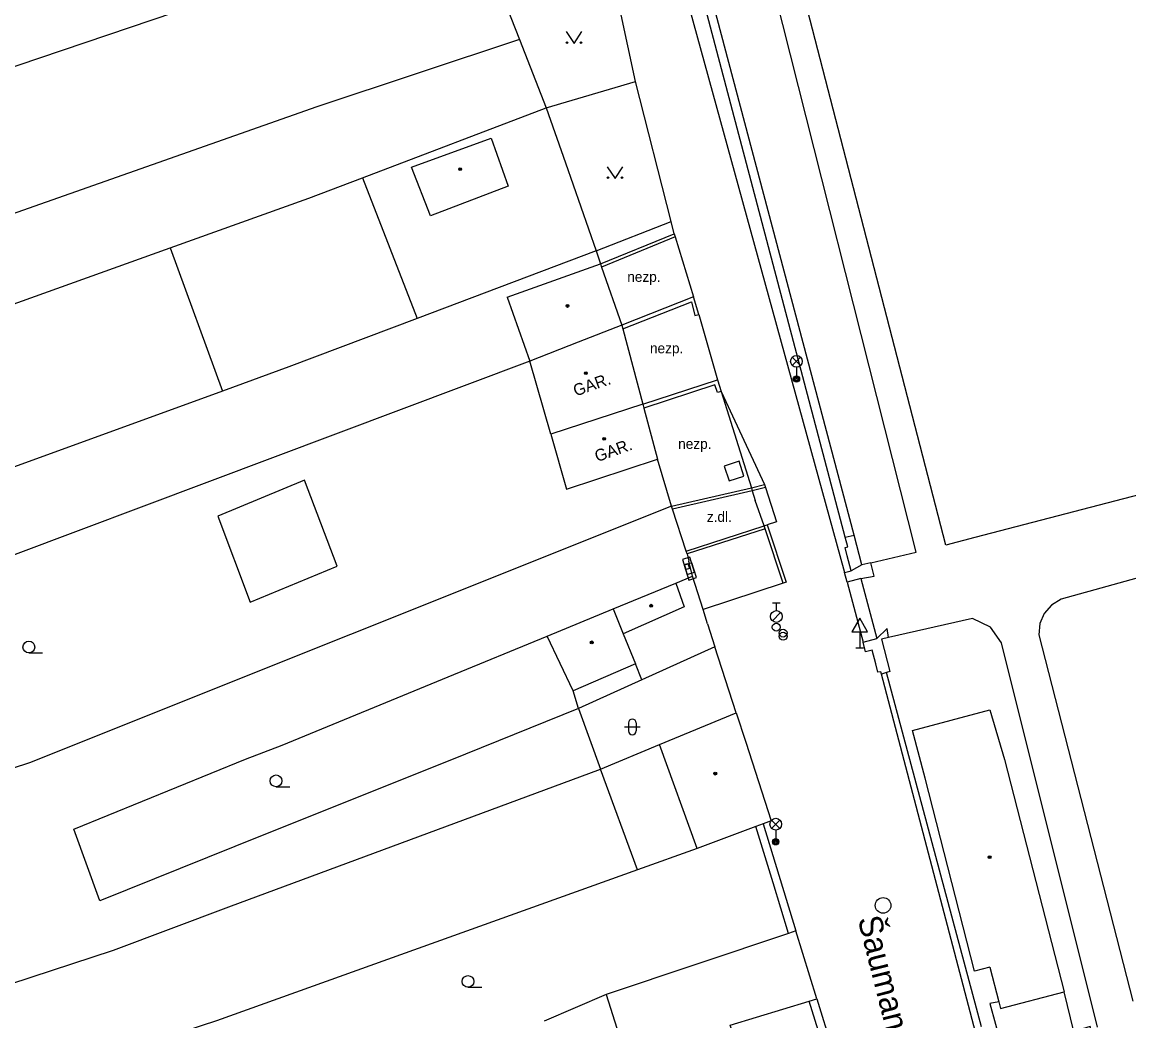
# Model space of a CAD drawing. Extents: x -595546 to -593986, y -1160845 to -1159202.
# Drawn here: x -595377.5 to -595306.9, y -1160103.9 to -1160040.2 of the extents above; entities that cross this region are included whole.
import ezdxf

# ---------------------------------------------------------------- set-up
doc = ezdxf.new("R2010")
doc.units = 0
for name, color, linetype in [('DOP - budovy nerozlisene - VP', 7, 'Continuous'), ('DOP - kresba z DSPS bez souradnic', 7, 'Continuous'), ('DOP - rozhrani ploch obecne', 7, 'Continuous'), ('Level 24', 7, 'Continuous'), ('Level 26', 7, 'Continuous'), ('Level 27', 7, 'Continuous'), ('Level 28', 7, 'Continuous'), ('Level 33', 7, 'Continuous'), ('Level 34', 7, 'Continuous'), ('Level 36', 7, 'Continuous'), ('Level 39', 7, 'Continuous'), ('Nazvy ulic', 7, 'Continuous'), ('silnoproud - povrch.  znaky a  RIS  skut. velikost', 7, 'Continuous'), ('Specificka linie pasportu komunikaci', 7, 'Continuous'), ('TM - budovy zdene_ betonove - VP', 7, 'Continuous'), ('TM - chodniky - VP', 7, 'Continuous'), ('TM - komunikace - VP', 7, 'Continuous'), ('TM - letecke snimky - pomocna linie', 7, 'Continuous'), ('TM - plot drateny_ kovovy - VP', 7, 'Continuous'), ('TM - podezdivka plotu - VP', 7, 'Continuous'), ('TM - popis objektu', 7, 'Continuous'), ('TM - popis povrchu', 7, 'Continuous'), ('TM - rozhrani ploch obecne - VP', 7, 'Continuous'), ('TM - vjezd na pozemek', 7, 'Continuous')]:
    doc.layers.add(name, color=color, linetype=linetype)

msp = doc.modelspace()

# ---------------------------------------------------------------- linework, layer by layer
at = {"layer": 'DOP - budovy nerozlisene - VP'}
for points in [[(-595352.7, -1160049.44), (-595347.6, -1160047.6)], [(-595347.6, -1160047.6), (-595346.52, -1160050.65)], [(-595351.49, -1160052.54), (-595352.7, -1160049.44)], [(-595346.52, -1160050.65), (-595351.49, -1160052.54)]]:
    msp.add_lwpolyline(points, dxfattribs=at)
at = {"layer": 'DOP - kresba z DSPS bez souradnic'}
for points in [[(-595320.47, -1160074.01), (-595330.51, -1160034.34), (-595292.71, -1160024.25)], [(-595318.59, -1160073.57), (-595327.9, -1160037.48), (-595292.42, -1160027.98)], [(-595283.02, -1160064.31), (-595316.73, -1160073.08), (-595318.59, -1160073.57)], [(-595276.28, -1160087.45), (-595280.92, -1160070.28), (-595281.28, -1160069.71), (-595281.79, -1160069.34), (-595282.39, -1160069.15), (-595283.06, -1160069.2), (-595311.22, -1160077.02)], [(-595311.22, -1160077.02), (-595311.84, -1160077.39), (-595312.31, -1160077.92), (-595312.58, -1160078.57), (-595312.64, -1160079.3), (-595306.64, -1160102.66)], [(-595315.73, -1160078.79), (-595316.88, -1160078.25)], [(-595315.02, -1160079.8), (-595315.73, -1160078.79)], [(-595308.9, -1160104.34), (-595315.02, -1160079.8)]]:
    msp.add_lwpolyline(points, dxfattribs=at)
at = {"layer": 'DOP - rozhrani ploch obecne'}
for points in [[(-595397.89, -1160049.71), (-595349.19, -1160033.22)], [(-595345.8, -1160041.3), (-595358.73, -1160045.59)], [(-595358.73, -1160045.59), (-595440.25, -1160074.28)], [(-595355.83, -1160050.13), (-595344.09, -1160045.65)], [(-595359.25, -1160051.43), (-595355.83, -1160050.13)], [(-595368.1, -1160054.6), (-595359.25, -1160051.43)], [(-595438.69, -1160079.91), (-595368.1, -1160054.6)], [(-595340.91, -1160054.79), (-595352.34, -1160059.1)], [(-595352.34, -1160059.1), (-595360.52, -1160062.19)], [(-595345.13, -1160061.83), (-595398.63, -1160081.9)], [(-595360.52, -1160062.19), (-595364.76, -1160063.73)], [(-595364.76, -1160063.73), (-595435.62, -1160089.5)], [(-595336.1, -1160071.08), (-595377.07, -1160087.46)], [(-595350.35, -1160081.96), (-595344.04, -1160079.37)], [(-595360.95, -1160086.34), (-595350.35, -1160081.96)], [(-595342.03, -1160084), (-595349.24, -1160086.91)], [(-595342.03, -1160084), (-595340.62, -1160087.86)], [(-595363.3, -1160087.23), (-595360.95, -1160086.34)], [(-595340.62, -1160087.86), (-595336.87, -1160086.29)], [(-595349.24, -1160086.91), (-595363.97, -1160092.79)], [(-595377.07, -1160087.46), (-595386.34, -1160090.48)], [(-595374.26, -1160091.7), (-595363.3, -1160087.23)], [(-595364.35, -1160096.65), (-595340.62, -1160087.86)], [(-595338.27, -1160094.29), (-595340.62, -1160087.86)], [(-595372.59, -1160096.27), (-595374.26, -1160091.7)], [(-595363.97, -1160092.79), (-595372.59, -1160096.27)], [(-595334.45, -1160092.92), (-595338.27, -1160094.29)], [(-595338.27, -1160094.29), (-595365.15, -1160103.92)], [(-595371.72, -1160099.41), (-595364.35, -1160096.65)], [(-595423.07, -1160116.24), (-595371.72, -1160099.41)], [(-595340.26, -1160102.25), (-595344.23, -1160103.94)], [(-595365.15, -1160103.92), (-595372.18, -1160106.22)]]:
    msp.add_lwpolyline(points, dxfattribs=at)
at = {"layer": 'Level 24'}
for points in [[(-595334.618, -1160075.291), (-595334.916, -1160074.336), (-595335.393, -1160074.486), (-595335.095, -1160075.44)], [(-595334.507, -1160075.64), (-595334.807, -1160074.686), (-595335.284, -1160074.836), (-595334.984, -1160075.79)]]:
    msp.add_lwpolyline(points, close=True, dxfattribs=at)
at = {"layer": 'Level 26'}
msp.add_lwpolyline([(-595332.423, -1160069.469), (-595331.471, -1160069.163), (-595331.777, -1160068.211), (-595332.729, -1160068.517)], close=True, dxfattribs=at)
at = {"layer": 'Level 27'}
msp.add_circle((-595322.59, -1160096.56), 0.5, dxfattribs=at)
at = {"layer": 'Level 28'}
for p, q in [((-595329.658, -1160078.392), (-595329.128, -1160077.862)), ((-595329.65, -1160077.245), (-595329.15, -1160077.245)), ((-595329.4, -1160077.745), (-595329.4, -1160077.245))]:
    msp.add_line(p, q, dxfattribs=at)
for centre, radius in [((-595329.4, -1160078.12), 0.375), ((-595329.41, -1160078.8), 0.25), ((-595328.97, -1160079.18), 0.25), ((-595328.97, -1160079.38), 0.25)]:
    msp.add_circle(centre, radius, dxfattribs=at)
at = {"layer": 'Level 33'}
for p, q in [((-595328.385, -1160062.1), (-595327.855, -1160061.57)), ((-595328.385, -1160061.57), (-595327.855, -1160062.1)), ((-595328.12, -1160062.21), (-595328.12, -1160062.96)), ((-595329.705, -1160091.64), (-595329.175, -1160091.11)), ((-595329.705, -1160091.11), (-595329.175, -1160091.64)), ((-595329.44, -1160091.75), (-595329.44, -1160092.5))]:
    msp.add_line(p, q, dxfattribs=at)
for centre, radius in [((-595328.12, -1160061.835), 0.375), ((-595328.12, -1160062.96), 0.2), ((-595328.12, -1160062.96), 0.145), ((-595328.12, -1160062.96), 0.0876), ((-595329.44, -1160091.375), 0.375), ((-595329.44, -1160092.5), 0.2), ((-595329.44, -1160092.5), 0.145), ((-595329.44, -1160092.5), 0.0876)]:
    msp.add_circle(centre, radius, dxfattribs=at)
at = {"layer": 'Level 34'}
for p, q in [((-595324.08, -1160079.102), (-595324.08, -1160080.12)), ((-595324.33, -1160080.12), (-595323.83, -1160080.12))]:
    msp.add_line(p, q, dxfattribs=at)
msp.add_lwpolyline([(-595324.58, -1160079.102), (-595323.58, -1160079.102), (-595324.08, -1160078.236)], close=True, dxfattribs=at)
at = {"layer": 'Level 36'}
for p, q in [((-595377.12, -1160080.445), (-595376.245, -1160080.445)), ((-595338.846, -1160084.916), (-595338.846, -1160085.416)), ((-595338.346, -1160084.916), (-595338.346, -1160085.416)), ((-595339.096, -1160085.166), (-595338.096, -1160085.166)), ((-595361.34, -1160088.985), (-595360.465, -1160088.985)), ((-595349.09, -1160101.785), (-595348.215, -1160101.785))]:
    msp.add_line(p, q, dxfattribs=at)
for points in [[(-595342.82, -1160040.79), (-595342.32, -1160041.54), (-595341.82, -1160040.79)], [(-595340.2, -1160049.41), (-595339.7, -1160050.16), (-595339.2, -1160049.41)]]:
    msp.add_lwpolyline(points, dxfattribs=at)
for centre, radius in [((-595342.77, -1160041.49), 0.05), ((-595341.871, -1160041.49), 0.05), ((-595340.15, -1160050.11), 0.05), ((-595339.251, -1160050.11), 0.05), ((-595377.12, -1160080.07), 0.375), ((-595361.34, -1160088.61), 0.375), ((-595349.09, -1160101.41), 0.375)]:
    msp.add_circle(centre, radius, dxfattribs=at)
for centre, start, end in [((-595338.596, -1160084.916), 0, 180), ((-595338.596, -1160085.416), 180, 0)]:
    msp.add_arc(centre, 0.25, start, end, dxfattribs=at)
at = {"layer": 'Level 39'}
for centre, radius in [((-595349.59, -1160049.57), 0.09), ((-595349.59, -1160049.57), 0.0398), ((-595342.73, -1160058.3), 0.09), ((-595342.73, -1160058.3), 0.0398), ((-595341.57, -1160062.59), 0.09), ((-595341.57, -1160062.59), 0.0398), ((-595340.39, -1160066.78), 0.09), ((-595340.39, -1160066.78), 0.0398), ((-595337.39, -1160077.43), 0.09), ((-595337.39, -1160077.43), 0.0398), ((-595341.19, -1160079.77), 0.09), ((-595341.19, -1160079.77), 0.0398), ((-595333.3, -1160088.15), 0.09), ((-595333.3, -1160088.15), 0.0398), ((-595315.79, -1160093.48), 0.09), ((-595315.79, -1160093.48), 0.0398)]:
    msp.add_circle(centre, radius, dxfattribs=at)
at = {"layer": 'silnoproud - povrch.  znaky a  RIS  skut. velikost'}
msp.add_lwpolyline([(-595334.95, -1160075.06), (-595335.16, -1160075.13), (-595335.26, -1160074.81), (-595335.05, -1160074.74), (-595334.95, -1160075.06)], dxfattribs=at)
at = {"layer": 'Specificka linie pasportu komunikaci'}
for points in [[(-595340.91, -1160054.79), (-595336.12, -1160052.9)], [(-595332.92, -1160063.75), (-595331, -1160069.9)], [(-595331, -1160069.9), (-595330.94, -1160070.09)], [(-595330.94, -1160070.09), (-595330.75, -1160070.71)], [(-595330.18, -1160072.33), (-595330.75, -1160070.71)], [(-595330.12, -1160072.52), (-595330.18, -1160072.33)]]:
    msp.add_lwpolyline(points, dxfattribs=at)
at = {"layer": 'TM - budovy zdene_ betonove - VP'}
for points in [[(-595346.59, -1160057.73), (-595340.63, -1160055.61)], [(-595340.63, -1160055.61), (-595340.56, -1160055.82)], [(-595340.56, -1160055.82), (-595339.27, -1160059.52)], [(-595346.59, -1160057.73), (-595345.13, -1160061.83)], [(-595339.27, -1160059.52), (-595342.06, -1160060.62)], [(-595339.27, -1160059.52), (-595339.21, -1160059.76)], [(-595339.21, -1160059.76), (-595337.93, -1160064.57)], [(-595342.06, -1160060.62), (-595345.13, -1160061.83)], [(-595343.8, -1160066.48), (-595345.13, -1160061.83)], [(-595337.93, -1160064.57), (-595343.8, -1160066.48)], [(-595337.93, -1160064.57), (-595337.86, -1160064.82)], [(-595337.86, -1160064.82), (-595336.99, -1160068.08)], [(-595343.8, -1160066.48), (-595342.79, -1160069.99)], [(-595342.79, -1160069.99), (-595336.99, -1160068.08)], [(-595339.82, -1160077.63), (-595335.81, -1160075.99)], [(-595335.81, -1160075.99), (-595335.29, -1160077.51)], [(-595344.04, -1160079.37), (-595339.82, -1160077.63)], [(-595339.82, -1160077.63), (-595339.18, -1160079.23)], [(-595335.29, -1160077.51), (-595339.18, -1160079.23)], [(-595339.18, -1160079.23), (-595338.4, -1160081.14)], [(-595342.37, -1160082.86), (-595344.04, -1160079.37)], [(-595338.4, -1160081.14), (-595342.37, -1160082.86)], [(-595336.87, -1160086.29), (-595331.97, -1160084.26)], [(-595331.97, -1160084.26), (-595331.36, -1160086.15)], [(-595334.45, -1160092.92), (-595336.87, -1160086.29)], [(-595331.36, -1160086.15), (-595329.74, -1160091.17)], [(-595314.84, -1160087.25), (-595311.02, -1160102.08)], [(-595316.76, -1160100.75), (-595319.91, -1160088.43)], [(-595330.24, -1160091.35), (-595330.71, -1160091.53)], [(-595329.74, -1160091.17), (-595330.24, -1160091.35)], [(-595330.71, -1160091.53), (-595334.45, -1160092.92)], [(-595315.78, -1160100.49), (-595316.76, -1160100.75)], [(-595315.78, -1160100.49), (-595315.21, -1160102.71)], [(-595315.1, -1160103.13), (-595311.02, -1160102.08)], [(-595315.21, -1160102.71), (-595315.1, -1160103.13)]]:
    msp.add_lwpolyline(points, dxfattribs=at)
at = {"layer": 'TM - chodniky - VP'}
for points in [[(-595323.38, -1160074.7), (-595320.47, -1160074.01)], [(-595316.88, -1160078.25), (-595322.25, -1160079.45)]]:
    msp.add_lwpolyline(points, dxfattribs=at)
at = {"layer": 'TM - komunikace - VP'}
for points in [[(-595338.4, -1160043.97), (-595340.78, -1160032.87)], [(-595335.91, -1160035.83), (-595325.05, -1160075.31)], [(-595336.12, -1160052.9), (-595338.4, -1160043.97)], [(-595335.92, -1160053.7), (-595336.12, -1160052.9)], [(-595335.86, -1160053.89), (-595334.69, -1160057.71)], [(-595334.36, -1160058.84), (-595333.16, -1160063.02)], [(-595332.92, -1160063.75), (-595330.15, -1160069.7)], [(-595330.09, -1160069.89), (-595329.4, -1160072.07), (-595329.99, -1160072.27)]]:
    msp.add_lwpolyline(points, dxfattribs=at)
at = {"layer": 'TM - letecke snimky - pomocna linie'}
for points in [[(-595355.83, -1160050.13), (-595352.34, -1160059.1)], [(-595368.1, -1160054.6), (-595364.76, -1160063.73)], [(-595359.52, -1160069.41), (-595365.05, -1160071.71), (-595362.99, -1160077.21)], [(-595362.99, -1160077.21), (-595357.45, -1160074.91), (-595359.52, -1160069.41)], [(-595328.97, -1160075.99), (-595334.08, -1160077.68)], [(-595319.91, -1160088.43), (-595320.71, -1160085.39), (-595315.77, -1160084.07), (-595314.84, -1160087.25)], [(-595328.62, -1160098.35), (-595340.26, -1160102.25)], [(-595328.15, -1160098.18), (-595328.62, -1160098.35)], [(-595326.82, -1160102.52), (-595328.15, -1160098.18)], [(-595340.26, -1160102.25), (-595337.02, -1160112.53)], [(-595330.32, -1160110.46), (-595332.35, -1160104.2), (-595327.3, -1160102.66)], [(-595327.3, -1160102.66), (-595326.82, -1160102.52)], [(-595315.21, -1160102.71), (-595315.78, -1160102.81), (-595314.69, -1160106.78), (-595309.62, -1160113.88), (-595307.16, -1160112.54), (-595309.38, -1160104.29), (-595310.41, -1160104.6), (-595311.02, -1160102.08)]]:
    msp.add_lwpolyline(points, dxfattribs=at)
at = {"layer": 'TM - plot drateny_ kovovy - VP'}
for points in [[(-595324.44, -1160072.93), (-595335.42, -1160031.5)], [(-595323.95, -1160074.82), (-595324.44, -1160072.93)], [(-595335.1, -1160074.13), (-595334.99, -1160074.58)], [(-595333.79, -1160078.58), (-595333.32, -1160080.06)], [(-595316.31, -1160104.31), (-595322.38, -1160081.7)]]:
    msp.add_lwpolyline(points, dxfattribs=at)
at = {"layer": 'TM - podezdivka plotu - VP'}
for points in [[(-595325, -1160073.06), (-595334.9, -1160035.57)], [(-595340.63, -1160055.61), (-595335.92, -1160053.7)], [(-595335.86, -1160053.89), (-595340.56, -1160055.82)], [(-595335.92, -1160053.7), (-595335.86, -1160053.89)], [(-595334.69, -1160057.71), (-595339.27, -1160059.52)], [(-595339.21, -1160059.76), (-595334.83, -1160058.04)], [(-595334.83, -1160058.04), (-595334.6, -1160058.91), (-595334.36, -1160058.84)], [(-595334.36, -1160058.84), (-595334.69, -1160057.71)], [(-595337.93, -1160064.57), (-595333.16, -1160063.02)], [(-595333.16, -1160063.02), (-595332.92, -1160063.75)], [(-595333.32, -1160063.34), (-595337.86, -1160064.82)], [(-595332.92, -1160063.75), (-595333.16, -1160063.83), (-595333.32, -1160063.34)], [(-595336.1, -1160071.08), (-595331, -1160069.9)], [(-595330.94, -1160070.09), (-595336.04, -1160071.26)], [(-595331, -1160069.9), (-595330.15, -1160069.7)], [(-595330.09, -1160069.89), (-595330.94, -1160070.09)], [(-595330.15, -1160069.7), (-595330.09, -1160069.89)], [(-595336.04, -1160071.26), (-595336.1, -1160071.08)], [(-595330.18, -1160072.33), (-595329.99, -1160072.27)], [(-595329.99, -1160072.27), (-595328.78, -1160075.93), (-595328.97, -1160075.99)], [(-595335.16, -1160073.94), (-595330.18, -1160072.33)], [(-595330.12, -1160072.52), (-595335.1, -1160074.13)], [(-595328.97, -1160075.99), (-595330.12, -1160072.52)], [(-595325.02, -1160073.72), (-595324.84, -1160073.67)], [(-595324.84, -1160073.67), (-595325, -1160073.06)], [(-595335.1, -1160074.13), (-595335.16, -1160073.94)], [(-595324.88, -1160074.25), (-595325.02, -1160073.72)], [(-595324.63, -1160075.2), (-595324.88, -1160074.25)], [(-595325.05, -1160075.31), (-595324.63, -1160075.2)], [(-595324.89, -1160075.93), (-595325.05, -1160075.31)], [(-595324, -1160075.7), (-595324.89, -1160075.93)], [(-595323.87, -1160079.75), (-595322.99, -1160079.52)], [(-595323.71, -1160080.38), (-595323.87, -1160079.75)], [(-595323.29, -1160080.27), (-595323.71, -1160080.38)], [(-595323.06, -1160081.14), (-595323.29, -1160080.27)], [(-595322.92, -1160081.67), (-595323.06, -1160081.14)], [(-595322.74, -1160081.65), (-595322.92, -1160081.67)], [(-595322.7, -1160081.79), (-595322.74, -1160081.65)], [(-595316.69, -1160104.65), (-595322.7, -1160081.79)]]:
    msp.add_lwpolyline(points, dxfattribs=at)
at = {"layer": 'TM - rozhrani ploch obecne - VP'}
for points in [[(-595347.83, -1160036.15), (-595345.8, -1160041.3)], [(-595345.8, -1160041.3), (-595344.09, -1160045.65)], [(-595344.09, -1160045.65), (-595338.4, -1160043.97)], [(-595344.09, -1160045.65), (-595342.87, -1160049.16)], [(-595342.87, -1160049.16), (-595340.91, -1160054.79)], [(-595340.91, -1160054.79), (-595340.63, -1160055.61)], [(-595325, -1160073.06), (-595324.44, -1160072.93)], [(-595334.76, -1160075.55), (-595334.99, -1160074.58)], [(-595323.95, -1160074.82), (-595324.63, -1160075.2)], [(-595324, -1160075.7), (-595323.15, -1160075.54), (-595323.38, -1160074.7)], [(-595323.38, -1160074.7), (-595323.95, -1160074.82)], [(-595335.81, -1160075.99), (-595334.76, -1160075.55)], [(-595334.08, -1160077.68), (-595334.76, -1160075.55)], [(-595324.89, -1160075.93), (-595323.87, -1160079.75)], [(-595333.79, -1160078.58), (-595334.08, -1160077.68)], [(-595322.25, -1160079.45), (-595322.32, -1160078.88), (-595322.99, -1160079.52)], [(-595333.32, -1160080.06), (-595337.99, -1160082.17)], [(-595322.25, -1160079.45), (-595322.69, -1160079.56)], [(-595322.69, -1160079.56), (-595322.15, -1160081.62), (-595322.38, -1160081.7)], [(-595337.99, -1160082.17), (-595338.4, -1160081.14)], [(-595337.99, -1160082.17), (-595342.03, -1160084)], [(-595322.38, -1160081.7), (-595322.7, -1160081.79)], [(-595342.03, -1160084), (-595342.37, -1160082.86)], [(-595330.24, -1160091.35), (-595328.15, -1160098.18)], [(-595328.62, -1160098.35), (-595329.61, -1160095.12), (-595330.71, -1160091.53)], [(-595325.38, -1160108.9), (-595327.3, -1160102.66)], [(-595326.82, -1160102.52), (-595324.91, -1160108.74)]]:
    msp.add_lwpolyline(points, dxfattribs=at)
at = {"layer": 'TM - vjezd na pozemek'}
for points in [[(-595336.1, -1160071.08), (-595336.99, -1160068.08)], [(-595335.16, -1160073.94), (-595336.04, -1160071.26)], [(-595324, -1160075.7), (-595322.99, -1160079.52)], [(-595331.97, -1160084.26), (-595333.32, -1160080.06)]]:
    msp.add_lwpolyline(points, dxfattribs=at)

# ---------------------------------------------------------------- texts
at = {"layer": 'Nazvy ulic'}
msp.add_text('Šaumannova', height=1.5, rotation=284.27383, dxfattribs=at).set_placement((-595324.217, -1160097.421))
at = {"layer": 'TM - popis objektu'}
for p in [(-595342.21, -1160064.08), (-595340.84, -1160068.27)]:
    msp.add_text('GAR.', height=0.75, rotation=19.54, dxfattribs=at).set_placement(p)
at = {"layer": 'TM - popis povrchu'}
for s, p in [('nezp.', (-595338.92, -1160056.76)), ('nezp.', (-595337.47, -1160061.32)), ('nezp.', (-595335.67, -1160067.42)), ('z.dl.', (-595333.84, -1160072.08))]:
    msp.add_text(s, height=0.65, dxfattribs=at).set_placement(p)

doc.saveas('drawing.dxf')
